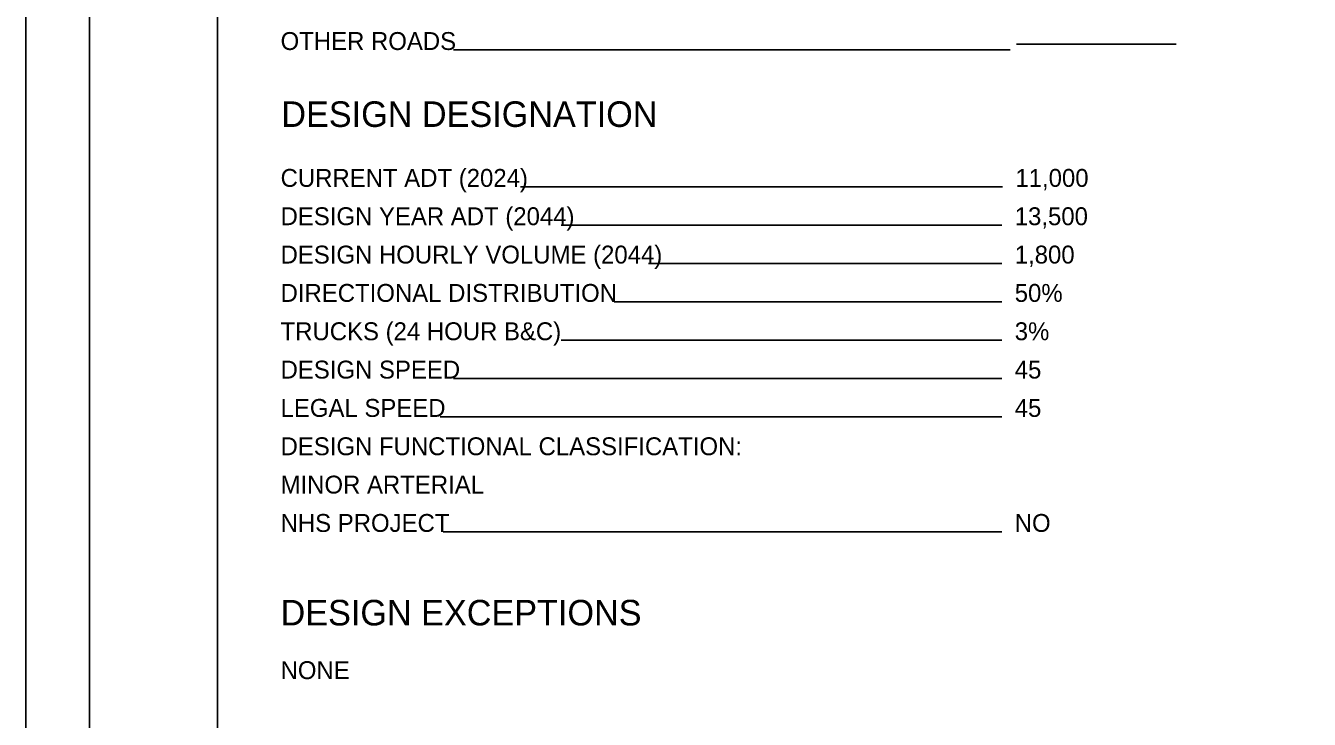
# Model space of a CAD drawing. Extents: x 0 to 34, y 0 to 22.
# Drawn here: x 0 to 10.04, y 5.64 to 11.07 of the extents above; entities that cross this region are included whole.
import ezdxf

# ---------------------------------------------------------------- set-up
doc = ezdxf.new("R2010")
doc.units = 0
for name, color, linetype in [('SH_Border', 7, 'Continuous'), ('SH_Cut_Line', 7, 'Continuous'), ('SH_Data', 7, 'Continuous'), ('SH_Text', 7, 'Continuous')]:
    doc.layers.add(name, color=color, linetype=linetype)

msp = doc.modelspace()

# ---------------------------------------------------------------- linework, layer by layer
at = {"layer": 'SH_Border'}
for points in [[(0.5, 21.5), (1.5, 21.5), (1.5, 0.5), (0.5, 0.5)], [(1.5, 21.5), (33.5, 21.5), (33.5, 0.5), (1.5, 0.5)]]:
    msp.add_lwpolyline(points, close=True, dxfattribs=at)
at = {"layer": 'SH_Cut_Line'}
msp.add_lwpolyline([(0, 0), (34, 0), (34, 22), (0, 22)], close=True, dxfattribs=at)
at = {"layer": 'SH_Data'}
for p, q in [((7.7, 10.877), (3.347, 10.877)), ((9, 10.922), (7.75, 10.922)), ((7.642, 9.806), (3.871, 9.806)), ((7.637, 9.506), (4.189, 9.506)), ((7.637, 9.206), (4.872, 9.206)), ((7.637, 8.906), (4.604, 8.906)), ((7.637, 8.606), (4.189, 8.606)), ((7.637, 8.306), (3.346, 8.306)), ((7.637, 8.006), (3.242, 8.006)), ((7.637, 7.106), (3.267, 7.106))]:
    msp.add_line(p, q, dxfattribs=at)

# ---------------------------------------------------------------- texts
msp.add_text('DESIGN DESIGNATION', height=0.2, dxfattribs=at).set_placement((2, 10.275))
at = {"layer": 'SH_Text'}
for s, height, p in [('OTHER ROADS', 0.14, (1.994, 10.877)), ('CURRENT ADT (2024)', 0.14, (1.994, 9.806)), ('11,000', 0.14, (7.742, 9.806)), ('DESIGN YEAR ADT (2044)', 0.14, (1.994, 9.506)), ('13,500', 0.14, (7.737, 9.506)), ('DESIGN HOURLY VOLUME (2044)', 0.14, (1.994, 9.206)), ('1,800', 0.14, (7.737, 9.206)), ('DIRECTIONAL DISTRIBUTION', 0.14, (1.994, 8.906)), ('50%', 0.14, (7.737, 8.906)), ('TRUCKS (24 HOUR B&C)', 0.14, (1.994, 8.606)), ('3%', 0.14, (7.737, 8.606)), ('DESIGN SPEED', 0.14, (1.994, 8.306)), ('45', 0.14, (7.737, 8.306)), ('LEGAL SPEED', 0.14, (1.994, 8.006)), ('45', 0.14, (7.737, 8.006)), ('DESIGN FUNCTIONAL CLASSIFICATION:', 0.14, (1.994, 7.706)), ('MINOR ARTERIAL', 0.14, (1.994, 7.406)), ('NHS PROJECT', 0.14, (1.994, 7.106)), ('NO', 0.14, (7.737, 7.106)), ('DESIGN EXCEPTIONS', 0.2, (1.994, 6.374)), ('NONE', 0.14, (1.994, 5.954))]:
    msp.add_text(s, height=height, dxfattribs=at).set_placement(p)

doc.saveas('drawing.dxf')
